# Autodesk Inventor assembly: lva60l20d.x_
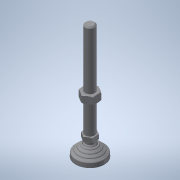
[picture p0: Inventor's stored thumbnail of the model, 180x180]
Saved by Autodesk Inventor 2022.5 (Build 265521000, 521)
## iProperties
Part Number: lva60l20d.x_
Material: 一般
Document SubType Name: Assembly
Designer: ImaoCorp
Sending System: SOLIDWORKS 2017-2017317
MC: AMD64
MC_MODEL: Intel64 Family 6 Model 60 Stepping 3, GenuineIntel
OS: Windows_NT
FRU: Parasolid Version 29.0, build 201,  4-17-2017
FORMAT: text
GUISE: transmit
KEY: lva60l20d
FILE: lva60l20d.x_t
DATE: Mon Jul 01 18:06:06 2019
Author: ImaoCorp
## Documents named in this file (3)
- X:\14_SW2022-Inv2022\00_全2023-1023新製品(TCC)まで\l\lva60l20d\LVA60L20D.iam
- X:\14_SW2022-Inv2022\00_全2023-1023新製品(TCC)まで\l\lva60l20d\lva60l20d_01.ipt
- X:\14_SW2022-Inv2022\00_全2023-1023新製品(TCC)まで\l\lva60l20d\lva60l20d_02.ipt
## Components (2 placed, 2 different names)
1. lva60l20d_01
2. lva60l20d_02
